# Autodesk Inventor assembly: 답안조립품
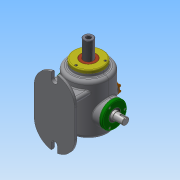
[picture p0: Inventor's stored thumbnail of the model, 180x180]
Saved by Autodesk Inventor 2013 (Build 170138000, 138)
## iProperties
Created: 2018-02
Part Number: 답안조립품
Document SubType Name: Assembly
Designer: Administrator
Mass: 7515.01 g
Surface Area: 3901.65 cm^2
Volume: 1791.88 cm^3
Density: 4.19393 g/cm^3
Author: Administrator
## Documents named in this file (16)
- C:\Users\Administrator\Desktop\380208V1006\답안조립품.iam
- C:\Users\Administrator\Desktop\380208V1006\본체.ipt
- C:\Users\Administrator\Desktop\380208V1006\베어링 6205.ipt
- 베어링 6205.ipt
- C:\Users\Administrator\Desktop\380208V1006\본체커버.ipt
- C:\Users\Administrator\Desktop\380208V1006\볼트 M4.ipt
- C:\Users\Administrator\Desktop\380208V1006\부시.ipt
- C:\Users\Administrator\Desktop\380208V1006\상부 캡.ipt
- C:\Users\Administrator\Desktop\380208V1006\슬라이드 커버.ipt
- C:\Users\Administrator\Desktop\380208V1006\슬라이드.ipt
- C:\Users\Administrator\Desktop\380208V1006\오일실.ipt
- 오일실.ipt
- C:\Users\Administrator\Desktop\380208V1006\축 커버-1.ipt
- C:\Users\Administrator\Desktop\380208V1006\축 커버-2.ipt
- C:\Users\Administrator\Desktop\380208V1006\편심축.ipt
- C:\Users\Administrator\Desktop\380208V1006\가변스프링.ipt
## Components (1 placed, 1 different names)
1. 가변스프링:1
